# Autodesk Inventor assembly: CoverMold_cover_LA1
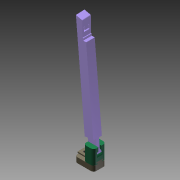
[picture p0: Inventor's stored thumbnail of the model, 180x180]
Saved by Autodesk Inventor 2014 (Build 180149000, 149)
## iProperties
Created: 2009-12
Part Number: CoverMold_cover_LA1
Document SubType Name: Assembly
Designer: gaom
Author: gaom
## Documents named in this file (4)
- C:\Users\iTools\Desktop\tutorial files\Mold\CoverMold\Cover Mold\Lifters\DME_Flat Core Blades 2\CoverMold_cover_LA1.iam
- C:\Users\iTools\Desktop\tutorial files\Mold\CoverMold\Cover Mold\Lifters\DME_Flat Core Blades 2\CoverMold_cover_LA1_ULG.ipt
- C:\Users\iTools\Desktop\tutorial files\Mold\CoverMold\Cover Mold\Lifters\DME_Flat Core Blades 2\CoverMold_cover_LA1_ULC.ipt
- C:\Users\iTools\Desktop\tutorial files\Mold\CoverMold\Cover Mold\Lifters\DME_Flat Core Blades 2\CoverMold_cover_LA1_ULB_Flat.ipt
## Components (3 placed, 3 different names)
1. CoverMold_cover_LA1_ULG:1 — Flush:1, Flush:2, Mate:1, Flush:3, Flush:4, Flush:5, Mate:2
2. CoverMold_cover_LA1_ULC:1 — Flush:3, Flush:4, Flush:5, Mate:3, Angle:1
3. CoverMold_cover_LA1_ULB_Flat:1 — Mate:2, Mate:3, Angle:1
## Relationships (9: Flush 5, Mate 3, Angle 1)
- Flush:1: CoverMold_cover_LA1_ULG:1
- Flush:2: CoverMold_cover_LA1_ULG:1
- Mate:1: CoverMold_cover_LA1_ULG:1
- Flush:3: CoverMold_cover_LA1_ULG:1 ↔ CoverMold_cover_LA1_ULC:1
- Flush:4: CoverMold_cover_LA1_ULG:1 ↔ CoverMold_cover_LA1_ULC:1
- Flush:5: CoverMold_cover_LA1_ULG:1 ↔ CoverMold_cover_LA1_ULC:1
- Mate:2: CoverMold_cover_LA1_ULG:1 ↔ CoverMold_cover_LA1_ULB_Flat:1
- Mate:3: CoverMold_cover_LA1_ULC:1 ↔ CoverMold_cover_LA1_ULB_Flat:1
- Angle:1: CoverMold_cover_LA1_ULC:1 ↔ CoverMold_cover_LA1_ULB_Flat:1
